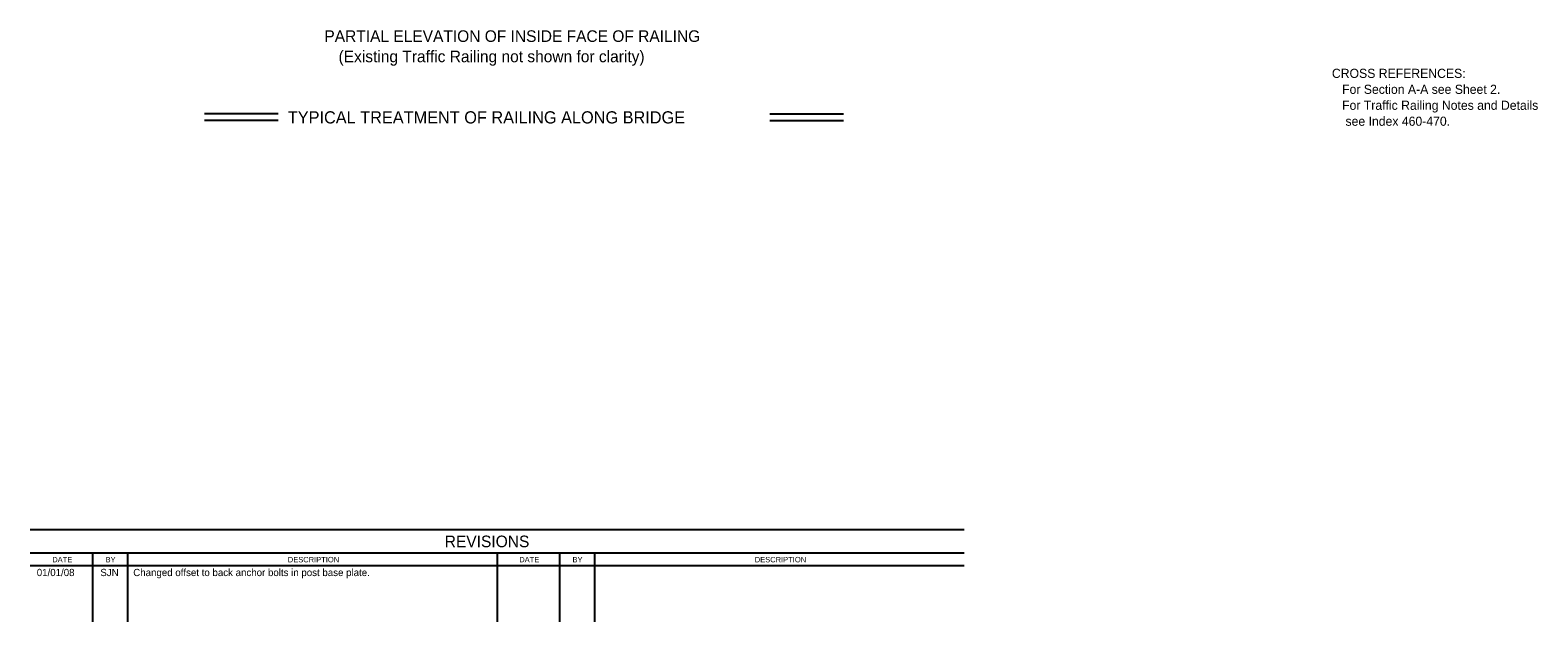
# Model space of a CAD drawing. Extents: x 21516.9 to 21586.2, y 56155.7 to 56195.
# Drawn here: x 21516.88 to 21550.15, y 56155.68 to 56168.73 of the extents above; entities that cross this region are included whole.
import ezdxf

# ---------------------------------------------------------------- set-up
doc = ezdxf.new("R2010")
doc.units = 0
for name, color, linetype in [('PlotBorder_dp', 7, 'Continuous'), ('SheetBorder_dp', 7, 'Continuous'), ('SheetLines_dp', 7, 'Continuous')]:
    doc.layers.add(name, color=color, linetype=linetype)

msp = doc.modelspace()

# ---------------------------------------------------------------- linework, layer by layer
at = {"layer": 'PlotBorder_dp'}
for p, q in [((21522.351, 56166.884), (21520.724, 56166.884)), ((21533.201, 56166.884), (21534.828, 56166.884)), ((21522.351, 56166.742), (21520.724, 56166.742)), ((21533.201, 56166.742), (21534.828, 56166.742))]:
    msp.add_line(p, q, dxfattribs=at)
at = {"layer": 'SheetLines_dp'}
for p, q in [((21537.488, 56157.708), (21516.877, 56157.708)), ((21537.488, 56157.193), (21516.877, 56157.193)), ((21518.253, 56157.193), (21518.253, 56155.678)), ((21519.027, 56157.193), (21519.027, 56155.678)), ((21527.183, 56157.193), (21527.183, 56155.678)), ((21528.559, 56157.193), (21528.559, 56155.678)), ((21529.333, 56157.193), (21529.333, 56155.678)), ((21516.877, 56156.92), (21537.488, 56156.92))]:
    msp.add_line(p, q, dxfattribs=at)

# ---------------------------------------------------------------- texts
at = {"layer": 'PlotBorder_dp'}
for s, height, p in [('PARTIAL ELEVATION OF INSIDE FACE OF RAILING', 0.256, (21523.371, 56168.473)), ('(Existing Traffic Railing not shown for clarity)', 0.256, (21523.683, 56168.025)), ('CROSS REFERENCES:', 0.2016, (21545.606, 56167.679)), ('   For Section A-A see Sheet 2.', 0.2016, (21545.606, 56167.327)), ('   For Traffic Railing Notes and Details ', 0.2016, (21545.606, 56166.975)), ('    see Index 460-470.', 0.2016, (21545.606, 56166.623))]:
    msp.add_text(s, height=height, dxfattribs=at).set_placement(p)
at = {"layer": 'SheetBorder_dp'}
for s, height, p in [('TYPICAL TREATMENT OF RAILING ALONG BRIDGE', 0.2688, (21522.563, 56166.674)), ('REVISIONS', 0.2567, (21526.025, 56157.324)), ('BY', 0.1201, (21518.541, 56156.99)), ('BY', 0.1201, (21528.847, 56156.99)), ('01/01/08', 0.16, (21517.023, 56156.687)), ('SJN', 0.16, (21518.426, 56156.687)), ('Changed offset to back anchor bolts in post base plate.', 0.16, (21519.152, 56156.687))]:
    msp.add_text(s, height=height, dxfattribs=at).set_placement(p)
for s, height, rotation, p in [('DATE', 0.1196, 359.8693, (21517.365, 56156.991)), ('DESCRIPTION', 0.12007, 0.0498, (21522.563, 56156.99)), ('DATE', 0.1196, 359.8693, (21527.671, 56156.991)), ('DESCRIPTION', 0.12007, 0.0498, (21532.869, 56156.99))]:
    msp.add_text(s, height=height, rotation=rotation, dxfattribs=at).set_placement(p)

doc.saveas('drawing.dxf')
